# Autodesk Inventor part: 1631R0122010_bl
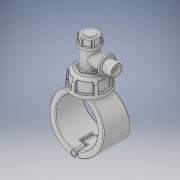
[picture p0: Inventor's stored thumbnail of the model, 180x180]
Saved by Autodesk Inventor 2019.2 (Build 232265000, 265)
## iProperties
Created: 2022-02
Part Number: 1631R0122010_bl
Material: Generic
Description: Plassadle Tapper Male 122x1''
Document SubType Name: Modeling
Designer: comp2
Density: 1 g/cm^3
Appearance: Default
Author: comp2
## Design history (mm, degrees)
derived "1631R.ipt"
feature "Solid1::1631R.ipt" dims "ScaleForDerivedMember" = 10
feature "Solid2::1631R.ipt" dims "ScaleForDerivedMember" = 10
feature "Solid3::1631R.ipt" dims "ScaleForDerivedMember" = 10
feature "Solid4::1631R.ipt" dims "ScaleForDerivedMember" = 10
tag "TaggingFeature1"
body "Solid1"
body "Solid2"
body "Solid3"
body "Solid4"
other parameters: "d0" = 122 [user parameter], "d2" = 157 [user parameter], "d3" = 61 [user parameter], "d7" = 149.15 [user parameter], "d8" = 85 deg [user parameter], "d9" = 45 deg [user parameter], "d10" = 102 [user parameter], "d11" = 49 [user parameter], "d12" = 34.3 [user parameter], "d13" = 42.84 [user parameter], "d14" = 57.936 [user parameter], "d15" = 2.45 [user parameter], "d16" = 2 [user parameter], "d17" = 2 [user parameter], "d18" = 29.4 [user parameter], "d19" = 7.35 [user parameter], "d20" = 1 [user parameter], "d21" = 30.6 [user parameter], "d22" = 1 [user parameter], "d23" = 14.7 [user parameter], "d24" = 78 [user parameter], "d27" = 144 [user parameter], "d29" = 49.8735 [user parameter], "d31" = 33.249 [user parameter], "d32" = 31.2 [user parameter], "d33" = 26.52 [user parameter], "d41" = 5 [user parameter], "d42" = 3.5 [user parameter], "d46" = 56.1 [user parameter], "d47" = 36.5739 [user parameter], "d48" = 49 [user parameter], "d49" = 3.14 [user parameter], "d51" = 0 [user parameter], "d52" = 24.5 [user parameter], "d53" = 86.35 [user parameter], "d54" = 35 [user parameter], "d55" = 0 [user parameter], "d59" = 0 [user parameter], "d61" = 0 [user parameter], "d62" = 35 [user parameter], "d63" = 0 [user parameter], "d65" = 0 [user parameter], "d67" = 0 [user parameter], "d69" = 0 [user parameter], "d70" = 1 [user parameter], "d71" = 96 [user parameter], "d72" = 0 [user parameter], "d73" = 2 [user parameter], "d77" = 24.93675 [user parameter], "d78" = 86.7 [user parameter], "d79" = 5.1 [user parameter], "d80" = 60 deg [user parameter], "d81" = 5.1 [user parameter], "d84" = 0 [user parameter], "d85" = 1 [user parameter], "d87" = 360 deg [user parameter], "d90" = 0 [user parameter], "d91" = 1 [user parameter], "d93" = 60 deg [user parameter], "d94" = 3.06 [user parameter], "d95" = 3.06 [user parameter], "d97" = 0 [user parameter], "d98" = 0.5 [user parameter], "d100" = 360 deg [user parameter], "d102" = 2 [user parameter], "d117" = 0.5 [user parameter], "d118" = 31.2 [user parameter], "d119" = 100 deg [user parameter], "d121" = 0 [user parameter], "d" = 122 [user parameter], "d1" = 25 [user parameter], "B" = 157 [user parameter], "E_" = 54 [user parameter], "E1" = 102 [user parameter], "H2" = 144 [user parameter], "H3" = 78 [user parameter], "H_costum" = 49 [user parameter], "R" = 33.249 [user parameter]
